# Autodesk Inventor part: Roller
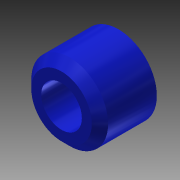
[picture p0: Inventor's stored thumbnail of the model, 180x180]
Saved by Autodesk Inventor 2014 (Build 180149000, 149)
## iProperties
Created: 2008-06
Part Number: Roller
Document SubType Name: Modeling
Designer: tangg
Density: 7.85 g/cm^3
Mass: 0.814587 g
Surface Area: 6.90277 cm^2
Volume: 0.814587 cm^3
Material: Non-Alloy Steel
Appearance: Blue - Wall Paint - Glossy
Author: tangg
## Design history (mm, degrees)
sketch "Sketch1"
  geometry: C1 r 6 at (0, 0); C2 r 3.175 at (0, 0); 1 further point
  constraints: 2 centre point, 1 coincident
  dimensions: "d4" = 6.35 diameter of C2; "d5" = 12 diameter of C1
extrude "Extrusion2" new body sketch "Sketch1" distance "d2" = 8.89; taper "d3" = 0 deg
chamfer "Chamfer1" distance "d6" = 1.27; stored, may be unused: second distance "d7" = 3.175, angle "d8" = 45 deg
workpoint "Work Point1"
  workplane "Work Plane1"
body "Solid1"
other parameters: "d9" = -2.54
